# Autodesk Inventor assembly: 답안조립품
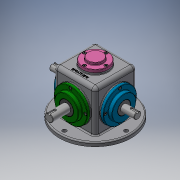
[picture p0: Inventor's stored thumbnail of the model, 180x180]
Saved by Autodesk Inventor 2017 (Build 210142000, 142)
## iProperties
Part Number: 답안조립품
Material: 일반
Document SubType Name: Assembly
Designer: 00-00
Author: 00-00
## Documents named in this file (15)
- C:\Users\00-00\Desktop\601004V1017\답안조립품.iam
- C:\Users\00-00\Desktop\601004V1017\본체.ipt
- C:\Users\00-00\Desktop\601004V1017\메인베벨기어.ipt
- C:\Users\00-00\Desktop\601004V1017\메인축.ipt
- C:\Users\00-00\Desktop\601004V1017\메인커버.ipt
- C:\Users\00-00\Desktop\601004V1017\베어링 6203.ipt
- C:\Users\00-00\Desktop\601004V1017\베어링 6204.ipt
- C:\Users\00-00\Desktop\601004V1017\볼트 M4.ipt
- C:\Users\00-00\Desktop\601004V1017\상부커버.ipt
- C:\Users\00-00\Desktop\601004V1017\서브베벨기어.ipt
- C:\Users\00-00\Desktop\601004V1017\서브축.ipt
- C:\Users\00-00\Desktop\601004V1017\서브커버.ipt
- C:\Users\00-00\Desktop\601004V1017\오일 실 17 32 8.ipt
- C:\Users\00-00\Desktop\601004V1017\오일 실 20 35 8.ipt
- C:\Users\00-00\Desktop\601004V1017\키 4x4.ipt
## Named parameters: d10_d8 = 0, d11_d9 = 0
